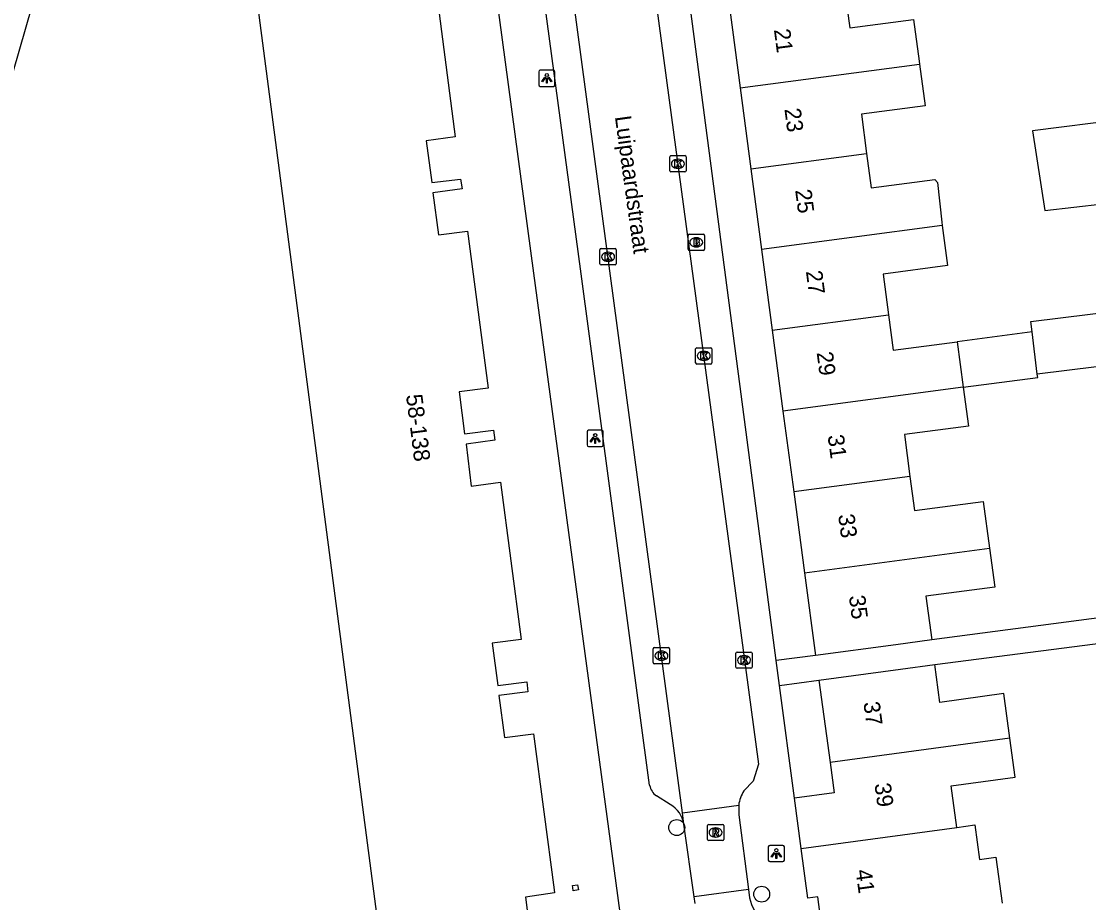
# Model space of a CAD drawing. Extents: x 163150 to 163546, y 380933 to 381635.
# Drawn here: x 163226.9 to 163292.5, y 381344.9 to 381399.1 of the extents above; entities that cross this region are included whole.
import ezdxf

# ---------------------------------------------------------------- set-up
doc = ezdxf.new("R2010")
doc.units = 0
for name, color, linetype in [('IMGEO_Boom', 7, 'Continuous'), ('IMGEO_Brandkraan', 7, 'Continuous'), ('IMGEO_Kolk', 7, 'Continuous'), ('IMGEO_Lichtpunt', 7, 'Continuous'), ('IMGEO_Openbare_ruimte_label', 7, 'Continuous'), ('IMGEO_Pand', 7, 'Continuous'), ('IMGEO_Pand_nummerreeks', 7, 'Continuous'), ('IMGEO_Rijbaan_lokaal_open', 7, 'Continuous'), ('IMGEO_Rioolput', 7, 'Continuous'), ('IMGEO_Voetpad_open', 7, 'Continuous')]:
    doc.layers.add(name, color=color, linetype=linetype)

msp = doc.modelspace()

# ---------------------------------------------------------------- linework, layer by layer
at = {"layer": 'IMGEO_Boom'}
for centre in [(163267.173, 381349.55), (163272.392, 381345.457)]:
    msp.add_circle(centre, 0.489, dxfattribs=at)
at = {"layer": 'IMGEO_Brandkraan'}
for p, q in [((163267.87, 381385.111), (163267.87, 381385.963)), ((163267.945, 381386.037), (163268.797, 381386.037)), ((163268.358, 381385.817), (163268.383, 381385.817)), ((163268.871, 381385.963), (163268.871, 381385.111)), ((163268.797, 381385.037), (163267.945, 381385.037)), ((163268.381, 381385.257), (163268.356, 381385.257))]:
    msp.add_line(p, q, dxfattribs=at)
for points in [[(163267.87, 381385.111), (163267.87, 381385.963)], [(163267.945, 381386.037), (163268.797, 381386.037)], [(163268.218, 381385.737), (163268.218, 381385.337), (163268.431, 381385.337)], [(163268.449, 381385.737), (163268.218, 381385.737)], [(163268.397, 381385.656), (163268.343, 381385.656), (163268.343, 381385.58)], [(163268.343, 381385.58), (163268.396, 381385.58)], [(163268.871, 381385.963), (163268.871, 381385.111)], [(163268.797, 381385.037), (163267.945, 381385.037)], [(163268.405, 381385.504), (163268.343, 381385.504), (163268.343, 381385.423)], [(163268.343, 381385.423), (163268.405, 381385.423)]]:
    msp.add_lwpolyline(points, dxfattribs=at)
for centre, radius, start, end in [((163267.947, 381385.961), 0.0765, 91.55205, 178.44795), ((163267.947, 381385.961), 0.0765, 91.55205, 178.44795), ((163268.398, 381385.618), 0.0379, 267.82845, 90.93552), ((163268.453, 381385.592), 0.145, 59.4692, 91.53667), ((163268.478, 381385.639), 0.0922, 285.51372, 58.15012), ((163268.483, 381385.447), 0.105, 301.31148, 78.98903), ((163268.795, 381385.961), 0.0765, 1.55205, 88.44795), ((163268.795, 381385.961), 0.0765, 1.55205, 88.44795), ((163267.947, 381385.113), 0.0765, 181.55205, 268.44795), ((163267.947, 381385.113), 0.0765, 181.55205, 268.44795), ((163268.406, 381385.463), 0.0404, 269.87594, 90.50774), ((163268.437, 381385.588), 0.251, 268.66757, 293.53466), ((163268.795, 381385.113), 0.0765, 271.55205, 358.44795), ((163268.795, 381385.113), 0.0765, 271.55205, 358.44795)]:
    msp.add_arc(centre, radius, start, end, dxfattribs=at)
for centre, major_axis, ratio, start_param, end_param in [((163268.357, 381385.537), (-0.387, 0.002), 0.722429, 4.712389, 7.853982), ((163268.382, 381385.537), (-0.39, 0.002), 0.717154, 1.570796, 4.712389)]:
    msp.add_ellipse(centre, major_axis=major_axis, ratio=ratio, start_param=start_param, end_param=end_param, dxfattribs=at)
at = {"layer": 'IMGEO_Kolk'}
for p, q in [((163266.742, 381389.94), (163266.742, 381390.792)), ((163266.817, 381390.866), (163267.669, 381390.866)), ((163267.743, 381390.792), (163267.743, 381389.94)), ((163267.23, 381390.646), (163267.255, 381390.646)), ((163267.669, 381389.866), (163266.817, 381389.866)), ((163267.253, 381390.086), (163267.228, 381390.086)), ((163262.45, 381384.223), (163262.45, 381385.075)), ((163262.525, 381385.149), (163263.377, 381385.149)), ((163262.938, 381384.929), (163262.963, 381384.929)), ((163263.451, 381385.075), (163263.451, 381384.223)), ((163262.961, 381384.369), (163262.936, 381384.369)), ((163263.377, 381384.149), (163262.525, 381384.149)), ((163268.333, 381378.127), (163268.333, 381378.979)), ((163268.408, 381379.053), (163269.26, 381379.053)), ((163269.334, 381378.979), (163269.334, 381378.127)), ((163268.821, 381378.833), (163268.846, 381378.833)), ((163269.26, 381378.053), (163268.408, 381378.053)), ((163268.844, 381378.273), (163268.819, 381378.273)), ((163265.803, 381360.618), (163266.655, 381360.618)), ((163265.728, 381359.692), (163265.728, 381360.544)), ((163266.216, 381360.398), (163266.241, 381360.398)), ((163266.729, 381360.544), (163266.729, 381359.692)), ((163270.806, 381359.419), (163270.806, 381360.271)), ((163270.881, 381360.345), (163271.733, 381360.345)), ((163271.294, 381360.125), (163271.319, 381360.125)), ((163271.807, 381360.271), (163271.807, 381359.419)), ((163266.655, 381359.618), (163265.803, 381359.618)), ((163266.239, 381359.838), (163266.214, 381359.838)), ((163271.733, 381359.345), (163270.881, 381359.345)), ((163271.317, 381359.565), (163271.292, 381359.565))]:
    msp.add_line(p, q, dxfattribs=at)
for points in [[(163266.742, 381389.94), (163266.742, 381390.792)], [(163266.817, 381390.866), (163267.669, 381390.866)], [(163267.743, 381390.792), (163267.743, 381389.94)], [(163267.063, 381390.566), (163267.186, 381390.566), (163267.186, 381390.415), (163267.316, 381390.566), (163267.48, 381390.566), (163267.334, 381390.415), (163267.487, 381390.166), (163267.335, 381390.166), (163267.25, 381390.33), (163267.186, 381390.263), (163267.186, 381390.166), (163267.063, 381390.166), (163267.063, 381390.566)], [(163267.669, 381389.866), (163266.817, 381389.866)], [(163262.45, 381384.223), (163262.45, 381385.075)], [(163262.525, 381385.149), (163263.377, 381385.149)], [(163263.451, 381385.075), (163263.451, 381384.223)], [(163262.771, 381384.849), (163262.894, 381384.849), (163262.894, 381384.698), (163263.024, 381384.849), (163263.188, 381384.849), (163263.042, 381384.698), (163263.195, 381384.449), (163263.043, 381384.449), (163262.958, 381384.613), (163262.894, 381384.546), (163262.894, 381384.449), (163262.771, 381384.449), (163262.771, 381384.849)], [(163263.377, 381384.149), (163262.525, 381384.149)], [(163268.333, 381378.127), (163268.333, 381378.979)], [(163268.408, 381379.053), (163269.26, 381379.053)], [(163269.334, 381378.979), (163269.334, 381378.127)], [(163268.654, 381378.753), (163268.777, 381378.753), (163268.777, 381378.602), (163268.907, 381378.753), (163269.071, 381378.753), (163268.925, 381378.602), (163269.078, 381378.353), (163268.926, 381378.353), (163268.841, 381378.517), (163268.777, 381378.45), (163268.777, 381378.353), (163268.654, 381378.353), (163268.654, 381378.753)], [(163269.26, 381378.053), (163268.408, 381378.053)], [(163265.803, 381360.618), (163266.655, 381360.618)], [(163265.728, 381359.692), (163265.728, 381360.544)], [(163266.049, 381360.318), (163266.172, 381360.318), (163266.172, 381360.167), (163266.302, 381360.318), (163266.466, 381360.318), (163266.32, 381360.167), (163266.473, 381359.918), (163266.321, 381359.918), (163266.236, 381360.082), (163266.172, 381360.015), (163266.172, 381359.918), (163266.049, 381359.918), (163266.049, 381360.318)], [(163266.729, 381360.544), (163266.729, 381359.692)], [(163270.806, 381359.419), (163270.806, 381360.271)], [(163270.881, 381360.345), (163271.733, 381360.345)], [(163271.127, 381360.045), (163271.25, 381360.045), (163271.25, 381359.894), (163271.38, 381360.045), (163271.544, 381360.045), (163271.398, 381359.894), (163271.551, 381359.645), (163271.399, 381359.645), (163271.314, 381359.809), (163271.25, 381359.742), (163271.25, 381359.645), (163271.127, 381359.645), (163271.127, 381360.045)], [(163271.807, 381360.271), (163271.807, 381359.419)], [(163266.655, 381359.618), (163265.803, 381359.618)], [(163271.733, 381359.345), (163270.881, 381359.345)]]:
    msp.add_lwpolyline(points, dxfattribs=at)
for centre, start, end in [((163266.819, 381390.79), 91.55205, 178.44795), ((163266.819, 381390.79), 91.55205, 178.44795), ((163267.667, 381390.79), 1.55205, 88.44795), ((163267.667, 381390.79), 1.55205, 88.44795), ((163266.819, 381389.942), 181.55205, 268.44795), ((163266.819, 381389.942), 181.55205, 268.44795), ((163267.667, 381389.942), 271.55205, 358.44795), ((163267.667, 381389.942), 271.55205, 358.44795), ((163262.527, 381385.073), 91.55205, 178.44795), ((163262.527, 381385.073), 91.55205, 178.44795), ((163263.375, 381385.073), 1.55205, 88.44795), ((163263.375, 381385.073), 1.55205, 88.44795), ((163262.527, 381384.225), 181.55205, 268.44795), ((163262.527, 381384.225), 181.55205, 268.44795), ((163263.375, 381384.225), 271.55205, 358.44795), ((163263.375, 381384.225), 271.55205, 358.44795), ((163268.41, 381378.977), 91.55205, 178.44795), ((163268.41, 381378.977), 91.55205, 178.44795), ((163269.258, 381378.977), 1.55205, 88.44795), ((163269.258, 381378.977), 1.55205, 88.44795), ((163268.41, 381378.129), 181.55205, 268.44795), ((163268.41, 381378.129), 181.55205, 268.44795), ((163269.258, 381378.129), 271.55205, 358.44795), ((163269.258, 381378.129), 271.55205, 358.44795), ((163265.805, 381360.542), 91.55205, 178.44795), ((163265.805, 381360.542), 91.55205, 178.44795), ((163266.653, 381360.542), 1.55205, 88.44795), ((163266.653, 381360.542), 1.55205, 88.44795), ((163270.883, 381360.269), 91.55205, 178.44795), ((163270.883, 381360.269), 91.55205, 178.44795), ((163271.731, 381360.269), 1.55205, 88.44795), ((163271.731, 381360.269), 1.55205, 88.44795), ((163265.805, 381359.694), 181.55205, 268.44795), ((163265.805, 381359.694), 181.55205, 268.44795), ((163266.653, 381359.694), 271.55205, 358.44795), ((163266.653, 381359.694), 271.55205, 358.44795), ((163270.883, 381359.421), 181.55205, 268.44795), ((163270.883, 381359.421), 181.55205, 268.44795), ((163271.731, 381359.421), 271.55205, 358.44795), ((163271.731, 381359.421), 271.55205, 358.44795)]:
    msp.add_arc(centre, 0.0765, start, end, dxfattribs=at)
for centre, major_axis, ratio, start_param, end_param in [((163267.229, 381390.366), (-0.387, 0.002), 0.722429, 4.712389, 7.853982), ((163267.254, 381390.366), (-0.39, 0.002), 0.717154, 1.570796, 4.712389), ((163262.937, 381384.649), (-0.387, 0.002), 0.722429, 4.712389, 7.853982), ((163262.962, 381384.649), (-0.39, 0.002), 0.717154, 1.570796, 4.712389), ((163268.82, 381378.553), (-0.387, 0.002), 0.722429, 4.712389, 7.853982), ((163268.845, 381378.553), (-0.39, 0.002), 0.717154, 1.570796, 4.712389), ((163266.215, 381360.118), (-0.387, 0.002), 0.722429, 4.712389, 7.853982), ((163266.24, 381360.118), (-0.39, 0.002), 0.717154, 1.570796, 4.712389), ((163271.293, 381359.845), (-0.387, 0.002), 0.722429, 4.712389, 7.853982), ((163271.318, 381359.845), (-0.39, 0.002), 0.717154, 1.570796, 4.712389)]:
    msp.add_ellipse(centre, major_axis=major_axis, ratio=ratio, start_param=start_param, end_param=end_param, dxfattribs=at)
at = {"layer": 'IMGEO_Lichtpunt'}
for p, q in [((163258.687, 381396.026), (163258.687, 381395.219)), ((163258.687, 381396.026), (163258.687, 381395.219)), ((163259.589, 381396.121), (163258.781, 381396.121)), ((163259.589, 381396.121), (163258.781, 381396.121)), ((163259.683, 381395.219), (163259.683, 381396.026)), ((163259.683, 381395.219), (163259.683, 381396.026)), ((163258.781, 381395.125), (163259.589, 381395.125)), ((163258.781, 381395.125), (163259.589, 381395.125)), ((163261.66, 381373.882), (163261.66, 381373.075)), ((163261.66, 381373.882), (163261.66, 381373.075)), ((163262.562, 381373.977), (163261.754, 381373.977)), ((163262.562, 381373.977), (163261.754, 381373.977)), ((163262.656, 381373.075), (163262.656, 381373.882)), ((163262.656, 381373.075), (163262.656, 381373.882)), ((163261.754, 381372.981), (163262.562, 381372.981)), ((163261.754, 381372.981), (163262.562, 381372.981)), ((163272.795, 381348.357), (163272.795, 381347.55)), ((163272.795, 381348.357), (163272.795, 381347.55)), ((163273.697, 381348.452), (163272.889, 381348.452)), ((163273.697, 381348.452), (163272.889, 381348.452)), ((163273.791, 381347.55), (163273.791, 381348.357)), ((163273.791, 381347.55), (163273.791, 381348.357)), ((163272.889, 381347.456), (163273.697, 381347.456)), ((163272.889, 381347.456), (163273.697, 381347.456))]:
    msp.add_line(p, q, dxfattribs=at)
for points in [[(163259.061, 381395.69), (163259.1, 381395.662), (163258.912, 381395.4), (163258.874, 381395.427), (163259.061, 381395.69)], [(163259.163, 381395.642), (163259.21, 381395.642), (163259.21, 381395.32), (163259.163, 381395.32), (163259.163, 381395.642)], [(163259.273, 381395.662), (163259.311, 381395.689), (163259.498, 381395.427), (163259.459, 381395.399), (163259.273, 381395.662)], [(163262.034, 381373.546), (163262.073, 381373.518), (163261.885, 381373.256), (163261.847, 381373.283), (163262.034, 381373.546)], [(163262.136, 381373.498), (163262.183, 381373.498), (163262.183, 381373.176), (163262.136, 381373.176), (163262.136, 381373.498)], [(163262.246, 381373.518), (163262.284, 381373.545), (163262.471, 381373.283), (163262.432, 381373.255), (163262.246, 381373.518)], [(163273.169, 381348.021), (163273.208, 381347.993), (163273.02, 381347.731), (163272.982, 381347.758), (163273.169, 381348.021)], [(163273.271, 381347.973), (163273.318, 381347.973), (163273.318, 381347.651), (163273.271, 381347.651), (163273.271, 381347.973)], [(163273.381, 381347.993), (163273.419, 381348.02), (163273.606, 381347.758), (163273.567, 381347.73), (163273.381, 381347.993)]]:
    msp.add_lwpolyline(points, dxfattribs=at)
for centre in [(163259.186, 381395.824), (163262.159, 381373.68), (163273.294, 381348.155)]:
    msp.add_circle(centre, 0.0994, dxfattribs=at)
for centre, start, end in [((163258.781, 381396.026), 90, 180), ((163258.781, 381396.026), 90, 180), ((163259.589, 381396.026), 0, 90), ((163259.589, 381396.026), 0, 90), ((163258.781, 381395.219), 180, 270), ((163258.781, 381395.219), 180, 270), ((163259.589, 381395.219), 270, 0), ((163259.589, 381395.219), 270, 360), ((163261.754, 381373.882), 90, 180), ((163261.754, 381373.882), 90, 180), ((163262.562, 381373.882), 0, 90), ((163262.562, 381373.882), 0, 90), ((163261.754, 381373.075), 180, 270), ((163261.754, 381373.075), 180, 270), ((163262.562, 381373.075), 270, 0), ((163262.562, 381373.075), 270, 360), ((163272.889, 381348.357), 90, 180), ((163272.889, 381348.357), 90, 180), ((163273.697, 381348.357), 0, 90), ((163273.697, 381348.357), 0, 90), ((163272.889, 381347.55), 180, 270), ((163272.889, 381347.55), 180, 270), ((163273.697, 381347.55), 270, 0), ((163273.697, 381347.55), 270, 360)]:
    msp.add_arc(centre, 0.0946, start, end, dxfattribs=at)
at = {"layer": 'IMGEO_Pand'}
for points in [[(163252.191, 381317.758), (163237.977, 381426.449)], [(163252.287, 381401.834), (163253.556, 381392.027), (163251.775, 381391.782), (163252.113, 381389.216), (163253.887, 381389.43), (163253.974, 381388.821), (163252.185, 381388.581), (163252.534, 381385.988), (163254.304, 381386.23), (163255.572, 381376.574), (163253.807, 381376.341), (163254.127, 381373.759), (163255.91, 381373.989), (163255.989, 381373.372), (163254.221, 381373.131), (163254.536, 381370.54), (163256.334, 381370.781), (163257.61, 381361.111), (163255.818, 381360.88), (163256.174, 381358.286), (163257.95, 381358.52), (163258.021, 381357.904), (163256.227, 381357.665), (163256.576, 381355.081), (163258.365, 381355.311), (163259.629, 381345.718), (163259.653, 381345.532), (163257.865, 381345.273), (163258.205, 381342.691)], [(163277.511, 381400.939), (163277.804, 381398.725), (163281.735, 381399.245), (163282.075, 381396.675), (163282.099, 381396.491)], [(163270.417, 381400), (163271.074, 381395.032)], [(163271.074, 381395.032), (163282.099, 381396.491)], [(163282.099, 381396.491), (163282.438, 381393.93), (163278.521, 381393.411), (163278.839, 381391.004)], [(163271.074, 381395.032), (163271.731, 381390.063)], [(163297.731, 381393.505), (163294.56, 381393.085), (163289.04, 381392.382), (163289.793, 381387.487), (163295.137, 381388.107)], [(163271.731, 381390.063), (163278.839, 381391.004)], [(163278.839, 381391.004), (163279.119, 381388.888), (163283.042, 381389.406), (163283.191, 381389.213), (163283.465, 381386.779), (163283.493, 381386.565)], [(163271.731, 381390.063), (163272.389, 381385.095)], [(163283.493, 381386.565), (163272.389, 381385.095)], [(163283.493, 381386.565), (163283.819, 381384.103), (163279.858, 381383.578), (163280.19, 381381.072)], [(163272.389, 381385.095), (163273.046, 381380.127)], [(163289.013, 381380.032), (163288.934, 381380.676), (163298.051, 381381.801), (163298.452, 381378.559), (163289.334, 381377.434)], [(163273.046, 381380.127), (163280.19, 381381.072)], [(163280.19, 381381.072), (163280.477, 381378.902), (163284.411, 381379.423)], [(163273.046, 381380.127), (163273.703, 381375.159)], [(163289.013, 381380.032), (163284.411, 381379.423)], [(163289.334, 381377.434), (163289.013, 381380.032)], [(163284.411, 381379.423), (163284.781, 381376.625)], [(163284.781, 381376.625), (163289.359, 381377.231), (163289.334, 381377.434)], [(163284.781, 381376.625), (163273.703, 381375.159)], [(163284.781, 381376.625), (163285.098, 381374.23), (163281.166, 381373.71), (163281.507, 381371.137)], [(163273.703, 381375.159), (163274.361, 381370.191)], [(163281.507, 381371.137), (163274.361, 381370.191)], [(163281.507, 381371.137), (163281.783, 381369.049), (163286.009, 381369.608), (163286.397, 381366.729)], [(163274.361, 381370.191), (163275.018, 381365.223)], [(163275.018, 381365.223), (163286.397, 381366.729)], [(163286.397, 381366.729), (163286.719, 381364.334), (163282.493, 381363.775), (163282.849, 381361.084)], [(163275.018, 381365.223), (163275.691, 381360.137)], [(163282.849, 381361.084), (163280.648, 381360.793), (163275.691, 381360.137)], [(163275.912, 381358.613), (163280.933, 381359.295), (163283.031, 381359.58)], [(163287.649, 381355.043), (163287.276, 381357.784), (163283.348, 381357.25), (163283.031, 381359.58)], [(163275.912, 381358.613), (163276.6, 381353.547)], [(163287.649, 381355.043), (163276.6, 381353.547)], [(163284.382, 381349.56), (163284.035, 381352.115), (163287.974, 381352.65), (163287.649, 381355.043)], [(163276.6, 381353.547), (163276.854, 381351.681), (163274.402, 381351.348)], [(163274.821, 381348.266), (163274.402, 381351.348)], [(163274.821, 381348.266), (163284.382, 381349.56)], [(163284.382, 381349.56), (163285.487, 381349.71), (163285.775, 381347.591), (163286.781, 381347.728), (163287.166, 381344.897)], [(163276.097, 381343.4), (163275.841, 381345.283), (163275.238, 381345.201), (163274.821, 381348.266)], [(163260.78, 381345.872), (163260.765, 381345.985), (163261.078, 381346.024), (163261.127, 381345.712), (163260.808, 381345.665), (163260.78, 381345.872)]]:
    msp.add_lwpolyline(points, dxfattribs=at)
at = {"layer": 'IMGEO_Rijbaan_lokaal_open'}
for points in [[(163267.521, 381350.462), (163258.589, 381417.14)], [(163263.928, 381415.028), (163272.206, 381353.444), (163271.867, 381352.413), (163271.298, 381351.803)], [(163267.521, 381350.462), (163270.978, 381350.93)], [(163270.978, 381350.93), (163270.98, 381350.323), (163271.587, 381345.735)], [(163267.615, 381349.759), (163267.521, 381350.462)], [(163268.239, 381345.283), (163267.615, 381349.759)], [(163271.587, 381345.735), (163268.239, 381345.283)], [(163271.587, 381345.735), (163271.653, 381345.233)], [(163268.295, 381344.88), (163268.239, 381345.283)]]:
    msp.add_lwpolyline(points, dxfattribs=at)
for centre, radius, start, end in [((163273.138, 381350.634), 2.18, 147.55541, 172.18355), ((163273.574, 381345.531), 1.944, 188.81821, 239.04348)]:
    msp.add_arc(centre, radius, start, end, dxfattribs=at)
at = {"layer": 'IMGEO_Rioolput'}
for p, q in [((163269.059, 381348.82), (163269.059, 381349.672)), ((163269.134, 381349.746), (163269.986, 381349.746)), ((163269.547, 381349.526), (163269.572, 381349.526)), ((163270.06, 381349.672), (163270.06, 381348.82)), ((163269.57, 381348.966), (163269.545, 381348.966)), ((163269.986, 381348.746), (163269.134, 381348.746))]:
    msp.add_line(p, q, dxfattribs=at)
for points in [[(163269.059, 381348.82), (163269.059, 381349.672)], [(163269.134, 381349.746), (163269.986, 381349.746)], [(163269.648, 381349.444), (163269.396, 381349.446), (163269.396, 381349.046)], [(163270.06, 381349.672), (163270.06, 381348.82)], [(163269.396, 381349.046), (163269.52, 381349.046), (163269.52, 381349.208), (163269.531, 381349.208)], [(163269.574, 381349.365), (163269.52, 381349.365), (163269.52, 381349.284)], [(163269.52, 381349.284), (163269.572, 381349.284)], [(163269.578, 381349.179), (163269.649, 381349.046), (163269.789, 381349.046), (163269.724, 381349.172)], [(163269.986, 381348.746), (163269.134, 381348.746)]]:
    msp.add_lwpolyline(points, dxfattribs=at)
for centre, radius, start, end in [((163269.136, 381349.67), 0.0765, 91.55205, 178.44795), ((163269.136, 381349.67), 0.0765, 91.55205, 178.44795), ((163269.647, 381349.334), 0.109, 350.36119, 89.41601), ((163269.984, 381349.67), 0.0765, 1.55205, 88.44795), ((163269.984, 381349.67), 0.0765, 1.55205, 88.44795), ((163269.136, 381348.822), 0.0765, 181.55205, 268.44795), ((163269.136, 381348.822), 0.0765, 181.55205, 268.44795), ((163269.53, 381349.155), 0.0533, 26.02933, 88.69889), ((163269.556, 381349.473), 0.19, 274.7715, 282.96867), ((163269.58, 381349.269), 0.0964, 77.00612, 93.18647), ((163269.594, 381349.326), 0.0378, 276.66336, 79.67722), ((163269.645, 381349.334), 0.112, 277.58423, 350.98172), ((163269.629, 381349.119), 0.108, 29.51342, 73.79051), ((163269.984, 381348.822), 0.0765, 271.55205, 358.44795), ((163269.984, 381348.822), 0.0765, 271.55205, 358.44795)]:
    msp.add_arc(centre, radius, start, end, dxfattribs=at)
for centre, major_axis, ratio, start_param, end_param in [((163269.546, 381349.246), (-0.387, 0.002), 0.722429, 4.712389, 7.853982), ((163269.571, 381349.246), (-0.39, 0.002), 0.717154, 1.570796, 4.712389)]:
    msp.add_ellipse(centre, major_axis=major_axis, ratio=ratio, start_param=start_param, end_param=end_param, dxfattribs=at)
at = {"layer": 'IMGEO_Voetpad_open'}
for points in [[(163270.661, 381292.68), (163258.396, 381383.641), (163252.391, 381428.393)], [(163237.977, 381426.449), (163234.394, 381426.061), (163227.903, 381401.347), (163219.779, 381373.21), (163217.039, 381362.987), (163210.152, 381338.67), (163208.061, 381330.864), (163204.278, 381316.746), (163202.976, 381313.355), (163198.372, 381299.184), (163184.779, 381256.196), (163183.349, 381256.587), (163188.12, 381274.155)], [(163265.506, 381352.152), (163261.263, 381383.916), (163257.164, 381414.367)], [(163273.289, 381359.821), (163266.729, 381409.746)], [(163301.552, 381364.672), (163301.697, 381363.577), (163282.849, 381361.084)], [(163283.031, 381359.58), (163301.955, 381362.021), (163302, 381361.67)], [(163275.691, 381360.137), (163273.289, 381359.821)], [(163273.489, 381358.295), (163273.289, 381359.821)], [(163273.489, 381358.295), (163275.912, 381358.613)], [(163274.402, 381351.348), (163273.489, 381358.295)], [(163266.773, 381350.959), (163265.92, 381351.494)]]:
    msp.add_lwpolyline(points, dxfattribs=at)
for centre, radius, start, end in [((163266.555, 381352.353), 1.068, 190.8342, 233.52031), ((163265.966, 381349.497), 1.67, 9.01451, 61.09761)]:
    msp.add_arc(centre, radius, start, end, dxfattribs=at)

# ---------------------------------------------------------------- texts
at = {"layer": 'IMGEO_Openbare_ruimte_label'}
msp.add_text('Luipaardstraat', height=1, rotation=277.81418, dxfattribs=at).set_placement((163263.367, 381393.26))
at = {"layer": 'IMGEO_Pand_nummerreeks'}
for s, rotation, p in [('21', 277.53727, (163273.142, 381398.614)), ('23', 277.53727, (163273.788, 381393.734)), ('25', 277.53727, (163274.448, 381388.742)), ('27', 277.53727, (163275.109, 381383.75)), ('29', 277.53727, (163275.769, 381378.758)), ('58-138', 277.16176, (163250.527, 381376.14)), ('31', 277.53727, (163276.445, 381373.654)), ('33', 277.53727, (163277.09, 381368.774)), ('35', 277.53727, (163277.751, 381363.782)), ('37', 277.73861, (163278.643, 381357.238)), ('39', 277.73861, (163279.323, 381352.23)), ('41', 277.74045, (163278.161, 381346.919))]:
    msp.add_text(s, height=1, rotation=rotation, dxfattribs=at).set_placement(p)

doc.saveas('drawing.dxf')
